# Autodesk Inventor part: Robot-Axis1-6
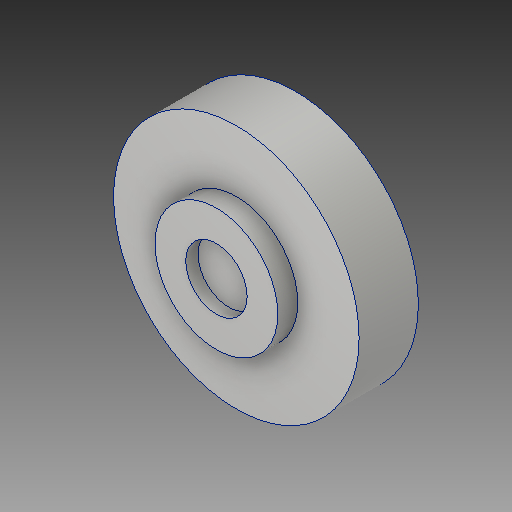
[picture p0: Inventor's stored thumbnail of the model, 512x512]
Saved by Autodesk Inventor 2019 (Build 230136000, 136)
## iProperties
Created: 2018-07
Part Number: Robot-Axis1-6
Material: Aluminum 6061
Description: 123456
Document SubType Name: Modeling
Designer: Power User
Mass: 280.594 g
Surface Area: 159.719 cm^2
Volume: 103.924 cm^3
Density: 2.7 g/cm^3
Appearance: Aluminum - Flat
Title: GEAR
Author: Power User
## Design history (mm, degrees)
sketch "Sketch6"
  geometry: C1 r 40 at (0, 0); C2 r 20 at (0, 0); 1 further point
  constraints: 2 centre point, 2 coincident
  dimensions: "d44" = 80 diameter of C1; "d45" = 40 diameter of C2
extrude "Extrusion5" new body sketch "Sketch6" distance "d46" = 19.3; taper "d47" = 0 deg
extrude "Extrusion6" join sketch "Sketch6" distance "d48" = 25.8; taper "d49" = 0 deg
sketch "Sketch7"
  geometry: C1 r 20 at (0, 0) reference; 2 further points
  constraints: 1 coincident
hole "Hole2" sketch "Sketch7" at (0, 0) diameter "d50" = 20; stored, may be unused: countersink angle "d54" = 90 deg, drill point angle "d56" = 0 deg; dims "d51" = 6, "d52" = 4, "d53" = 2, "d55" = 4
body "Solid2"
